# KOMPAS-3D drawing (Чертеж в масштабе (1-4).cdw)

Views: Вид 1
Referenced files in C:\Program Files\ASCON\KOMPAS-3D V10\Libs\: GRAPHIC.LFR|Крепежные элементы|Винт М12*50, GRAPHIC.LFR, GRAPHIC.LFR|Крепежные элементы|Шпонка 10-12, GRAPHIC.LFR|Крепежные элементы|Гайка М12
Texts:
  Параболическая зеркальная антенна со спиральным облучателем
  Текст на чертеже
  Размерные надписи
  Шероховатость
  Линия-выноска #1
  Линия-выноска #2
  Линия-выноска #3
  Отклонения формы и база
  Заголовок таблицы
  Ячейка таблицы
  Стрелка вида
  Обозначение изменения
  Фигурная скобка
  Номер узла
  Марка координационной оси
  VRCB
  Выносная надпись
  Обозначение узла
  Марка/позиционное обозначение с линией-выноской
  Марка/позиционное обозначение на линии
  Марка/позиционное обозначение без линии-выноски
  Крепежные элементы|Винт М12*50
  Крепежные элементы|Шпонка 10-12
  Крепежные элементы|Гайка М12
  Линия выноски #1
  Линия выноски #2
  Линия выноски #3
  cs 1
  cs 2
  сварка
  к передатчику
  Параболическая зеркальная
  антенна со спиральным
  облучателем
  Разраб.
  Беляков Л.С.
  Пров.
  Т.контр.
  Н.контр.
  Утв.
  МАИ
  Кафедра 406
  группа 04-427
Dimensions and other numbers on the sheet: 7; 1240; 1455; 70; 20; 1; 2; 3; 4; 5; 112; 96; 1:4; 24.11.08; 6; 8; 9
